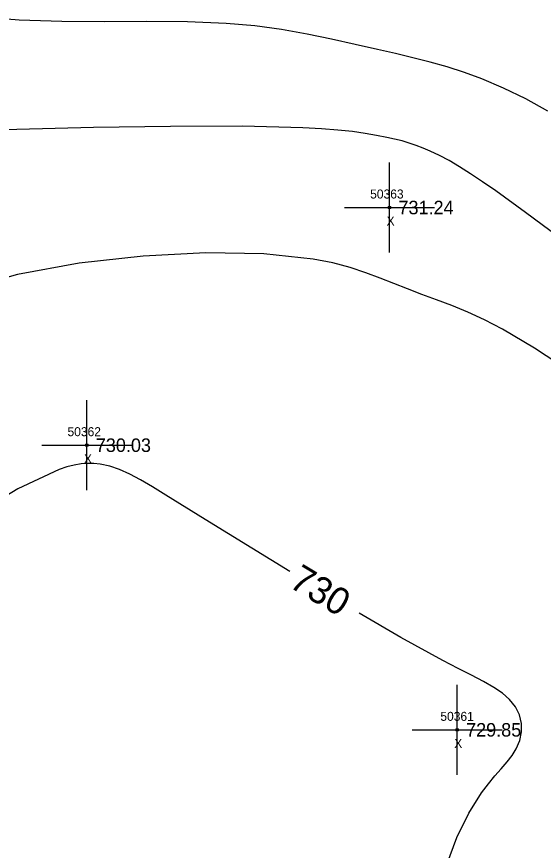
# Model space of a CAD drawing. Extents: x 1378535 to 1380697, y 997729 to 1000024.
# Drawn here: x 1379448.7 to 1379507.2, y 998967.1 to 999059.7 of the extents above; entities that cross this region are included whole.
import ezdxf

# ---------------------------------------------------------------- set-up
doc = ezdxf.new("R2010")
doc.units = 0
for name, color, linetype in [('RD_DTM_Major1', 7, 'Continuous'), ('RD_DTM_Major1_Lbl', 7, 'Continuous'), ('RD_DTM_Minor1', 7, 'Continuous'), ('RD_EX_Misc', 7, 'Continuous'), ('RD_EX_Misc_txCode', 7, 'Continuous'), ('RD_EX_TX_Misc_ELEV', 7, 'Continuous'), ('RD_SMD_Locator', 7, 'Continuous')]:
    doc.layers.add(name, color=color, linetype=linetype)

msp = doc.modelspace()

# ---------------------------------------------------------------- linework, layer by layer
at = {"layer": 'RD_DTM_Major1'}
for points in [[(1379479.065, 998998.058), (1379474.838, 999000.643), (1379469.669, 999003.837), (1379465.273, 999006.559), (1379463.81, 999007.457), (1379462.491, 999008.234), (1379461.283, 999008.884), (1379460.151, 999009.401), (1379459.06, 999009.778), (1379457.977, 999010.009), (1379457.301, 999010.075), (1379456.605, 999010.08), (1379455.88, 999010.02), (1379455.115, 999009.891), (1379454.302, 999009.689), (1379453.43, 999009.409), (1379448.835, 999007.267), (1379443.305, 999003.884)], [(1379496.501, 998965.512), (1379497.621, 998968.534), (1379498.943, 998971.219), (1379500.379, 998973.489), (1379501.131, 998974.474), (1379501.868, 998975.355), (1379502.568, 998976.158), (1379503.209, 998976.908), (1379503.769, 998977.631), (1379504.225, 998978.354), (1379504.624, 998979.29), (1379504.82, 998980.245), (1379504.808, 998981.199), (1379504.584, 998982.133), (1379504.142, 998983.027), (1379503.478, 998983.859), (1379502.695, 998984.544), (1379501.731, 998985.197), (1379500.588, 998985.853), (1379499.265, 998986.545), (1379497.763, 998987.307), (1379496.083, 998988.173), (1379491.403, 998990.743), (1379486.782, 998993.427)]]:
    msp.add_lwpolyline(points, dxfattribs=at)
at = {"layer": 'RD_DTM_Minor1'}
for points in [[(1379507.735, 999049.227), (1379505.277, 999050.563), (1379502.822, 999051.769), (1379500.391, 999052.814), (1379498.473, 999053.52), (1379496.569, 999054.128), (1379494.665, 999054.661), (1379492.748, 999055.145), (1379490.803, 999055.602), (1379488.816, 999056.058), (1379486.314, 999056.635), (1379483.714, 999057.215), (1379481, 999057.769), (1379478.155, 999058.265), (1379475.164, 999058.673), (1379472.011, 999058.964), (1379467.693, 999059.144), (1379463.156, 999059.173), (1379458.477, 999059.148), (1379453.733, 999059.165), (1379449.003, 999059.32), (1379444.364, 999059.708)], [(1379508.946, 999035.195), (1379505.247, 999037.954), (1379501.953, 999040.35), (1379500.49, 999041.369), (1379499.149, 999042.264), (1379497.914, 999043.044), (1379496.767, 999043.718), (1379495.692, 999044.294), (1379494.673, 999044.784), (1379493.886, 999045.118), (1379493.11, 999045.41), (1379492.332, 999045.667), (1379491.537, 999045.896), (1379490.713, 999046.103), (1379489.844, 999046.297), (1379488.702, 999046.524), (1379487.44, 999046.737), (1379486.023, 999046.933), (1379484.419, 999047.107), (1379482.592, 999047.255), (1379480.509, 999047.374), (1379473.813, 999047.535), (1379465.825, 999047.519), (1379457.239, 999047.381), (1379448.752, 999047.176), (1379441.058, 999046.959)], [(1379510.033, 999020.412), (1379506.265, 999022.891), (1379502.707, 999024.994), (1379500.713, 999026.017), (1379498.837, 999026.873), (1379497.059, 999027.603), (1379495.362, 999028.249), (1379493.724, 999028.853), (1379492.128, 999029.458), (1379490.638, 999030.055), (1379489.116, 999030.665), (1379487.509, 999031.266), (1379485.766, 999031.833), (1379483.833, 999032.344), (1379481.66, 999032.773), (1379476.163, 999033.35), (1379469.738, 999033.463), (1379462.776, 999033.114), (1379455.669, 999032.309), (1379448.806, 999031.05), (1379442.58, 999029.341)]]:
    msp.add_lwpolyline(points, dxfattribs=at)
at = {"layer": 'RD_EX_Misc'}
for p, q in [((1379490.137, 999033.506), (1379490.137, 999043.506)), ((1379485.137, 999038.506), (1379495.137, 999038.506)), ((1379456.505, 999007.1), (1379456.505, 999017.1)), ((1379451.505, 999012.1), (1379461.505, 999012.1)), ((1379497.653, 998975.476), (1379497.653, 998985.476)), ((1379492.653, 998980.476), (1379502.653, 998980.476))]:
    msp.add_line(p, q, dxfattribs=at)
at = {"layer": 'RD_SMD_Locator'}
for centre in [(1379490.137, 999038.506), (1379456.505, 999012.1), (1379497.653, 998980.476)]:
    msp.add_circle(centre, 0.15, dxfattribs=at)

# ---------------------------------------------------------------- texts
at = {"layer": 'RD_DTM_Major1_Lbl'}
msp.add_text('730', height=3, rotation=329.03273, dxfattribs=at).set_placement((1379478.844, 998996.427))
at = {"layer": 'RD_EX_Misc_txCode'}
for s, p in [('50363', (1379487.995, 999039.506)), ('X', (1379489.822, 999036.506)), ('50362', (1379454.363, 999013.1)), ('X', (1379456.19, 999010.1)), ('50361', (1379495.795, 998981.476)), ('X', (1379497.338, 998978.476))]:
    msp.add_text(s, height=1, dxfattribs=at).set_placement(p)
at = {"layer": 'RD_EX_TX_Misc_ELEV'}
for s, p in [('731.24', (1379491.137, 999037.756)), ('730.03', (1379457.505, 999011.35)), ('729.85', (1379498.653, 998979.726))]:
    msp.add_text(s, height=1.5, dxfattribs=at).set_placement(p)

doc.saveas('drawing.dxf')
